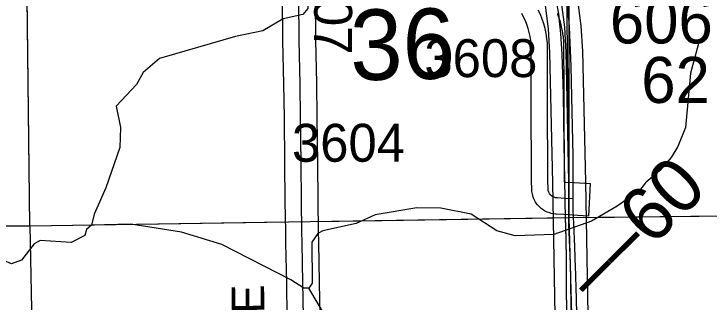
# Model space of a CAD drawing. Extents: x 23.6 to 68.7, y -63 to -29.
# Drawn here: x 43.707 to 44.988, y -51.736 to -51.204 of the extents above; entities that cross this region are included whole.
import ezdxf

# ---------------------------------------------------------------- set-up
doc = ezdxf.new("R2010")
doc.units = 0
for name, color, linetype in [('tdCoDivCarto', 7, 'Continuous'), ('tdCoHydroRiver', 7, 'Continuous'), ('tdCoPriCL', 7, 'Continuous'), ('tdCoPriDiv', 7, 'Continuous'), ('tdCoPrimary', 7, 'Continuous'), ('tdCoSecRdNmbr', 7, 'Continuous'), ('tdCoSecRdTxt', 7, 'Continuous'), ('tdCoSecRteBand', 7, 'Continuous'), ('tdCoSecRteCL', 7, 'Continuous'), ('tdCoSectLine', 7, 'Continuous'), ('tdCoSectLinePart', 7, 'Continuous'), ('tdCoSectNmbr', 7, 'Continuous'), ('tdCoStrucSecCoName', 7, 'Continuous'), ('tdCoStrucSecFHWANum', 7, 'Continuous'), ('tdCoSurfGravel', 7, 'Continuous'), ('tdCoTwpBndry', 7, 'Continuous'), ('tdCoTwpBndryShd', 7, 'Continuous'), ('tdStHwyPriRefPost1', 7, 'Continuous'), ('tdStHwyPriRefPost5', 7, 'Continuous')]:
    doc.layers.add(name, color=color, linetype=linetype)

msp = doc.modelspace()

# ---------------------------------------------------------------- linework, layer by layer
at = {"layer": 'tdCoDivCarto'}
for p, q in [((44.7304, -51.2183), (44.7201, -51.1354)), ((44.7304, -51.2183), (44.7293, -51.1793)), ((44.7103, -51.2035), (44.7105, -51.2055)), ((44.7105, -51.2055), (44.7142, -51.2401)), ((44.7309, -51.2279), (44.7304, -51.2183)), ((44.7341, -51.2999), (44.7309, -51.2279)), ((44.7142, -51.2401), (44.7164, -51.2781)), ((44.7164, -51.2781), (44.7179, -51.3156)), ((44.7354, -51.3847), (44.7341, -51.2999)), ((44.7179, -51.3156), (44.7183, -51.3329)), ((44.7183, -51.3329), (44.7188, -51.3523)), ((44.7188, -51.3523), (44.7203, -51.4443)), ((44.7373, -51.4649), (44.7354, -51.3847)), ((44.7203, -51.4443), (44.7221, -51.5441)), ((44.7373, -51.545), (44.7373, -51.4649)), ((44.7221, -51.5441), (44.723, -51.5846)), ((44.7373, -51.5665), (44.7373, -51.545)), ((44.7385, -51.5914), (44.7373, -51.5665)), ((44.723, -51.5846), (44.7232, -51.5939)), ((44.7406, -51.6331), (44.7385, -51.5914)), ((44.7232, -51.5939), (44.7245, -51.6539)), ((44.7419, -51.6729), (44.7406, -51.6331)), ((44.7245, -51.6539), (44.7246, -51.6659)), ((44.7246, -51.6659), (44.7247, -51.6852)), ((44.7246, -51.6659), (44.7247, -51.6852)), ((44.7423, -51.6829), (44.7419, -51.6729)), ((44.7423, -51.6829), (44.7419, -51.6729)), ((44.7425, -51.6895), (44.7423, -51.6829)), ((44.7247, -51.6852), (44.7248, -51.7095)), ((44.7247, -51.6852), (44.7248, -51.7095)), ((44.743, -51.7073), (44.7425, -51.6895)), ((44.7443, -51.7554), (44.743, -51.7073)), ((44.7248, -51.7095), (44.725, -51.754))]:
    msp.add_line(p, q, dxfattribs=at)
for points in [[(44.6843, -51.0826), (44.6868, -51.0888), (44.6905, -51.1011), (44.6964, -51.1248), (44.6991, -51.1413), (44.7103, -51.2035), (44.7105, -51.2055)], [(44.6843, -51.0826), (44.6868, -51.0888), (44.6905, -51.1011), (44.6964, -51.1248), (44.6991, -51.1413), (44.7103, -51.2035), (44.7105, -51.2055)], [(44.7309, -51.2279), (44.7304, -51.2183), (44.7293, -51.1793), (44.7254, -51.1263), (44.7241, -51.1111)], [(44.7309, -51.2279), (44.7304, -51.2183), (44.7293, -51.1793), (44.7254, -51.1263), (44.7241, -51.1111)], [(44.7309, -51.2279), (44.7304, -51.2183), (44.7293, -51.1793), (44.7254, -51.1263), (44.7241, -51.1111)], [(44.7304, -51.2183), (44.7201, -51.1354)], [(44.7304, -51.2183), (44.7201, -51.1354)], [(44.7304, -51.2183), (44.7201, -51.1354)], [(44.7103, -51.2035), (44.7142, -51.2401), (44.7164, -51.2781), (44.7179, -51.3156), (44.7183, -51.331)], [(44.7105, -51.2055), (44.7142, -51.2401), (44.7164, -51.2781), (44.7179, -51.3156), (44.7183, -51.3329)], [(44.7105, -51.2055), (44.7142, -51.2401), (44.7164, -51.2781), (44.7179, -51.3156), (44.7183, -51.3329)], [(44.7385, -51.5914), (44.7373, -51.5665), (44.7373, -51.545), (44.7373, -51.4649), (44.7354, -51.3847), (44.7341, -51.2999), (44.7309, -51.2279)], [(44.7385, -51.5914), (44.7373, -51.5665), (44.7373, -51.545), (44.7373, -51.4649), (44.7354, -51.3847), (44.7341, -51.2999), (44.7309, -51.2279)], [(44.7385, -51.5914), (44.7373, -51.5665), (44.7373, -51.545), (44.7373, -51.4649), (44.7354, -51.3847), (44.7341, -51.2999), (44.7309, -51.2279)], [(44.7183, -51.331), (44.7188, -51.3523), (44.7203, -51.4443), (44.7221, -51.5441), (44.723, -51.5846), (44.7232, -51.5919)], [(44.7183, -51.3329), (44.7188, -51.3523), (44.7203, -51.4443), (44.7221, -51.5441), (44.723, -51.5846), (44.7232, -51.5939)], [(44.7183, -51.3329), (44.7188, -51.3523), (44.7203, -51.4443), (44.7221, -51.5441), (44.723, -51.5846), (44.7232, -51.5939)], [(44.7232, -51.5919), (44.7245, -51.6539), (44.7246, -51.6639)], [(44.7419, -51.6729), (44.7406, -51.6331), (44.7385, -51.5914)], [(44.7419, -51.6729), (44.7406, -51.6331), (44.7385, -51.5914)], [(44.7419, -51.6729), (44.7406, -51.6331), (44.7385, -51.5914)], [(44.7232, -51.5939), (44.7245, -51.6539), (44.7246, -51.6659)], [(44.7232, -51.5939), (44.7245, -51.6539), (44.7246, -51.6659)], [(44.7246, -51.6639), (44.7247, -51.6832)], [(44.7246, -51.6659), (44.7247, -51.6852)], [(44.7247, -51.6832), (44.7248, -51.7075)], [(44.7423, -51.6829), (44.7419, -51.6729)], [(44.7423, -51.6829), (44.7419, -51.6729)], [(44.743, -51.7073), (44.7425, -51.6895), (44.7423, -51.6829)], [(44.743, -51.7073), (44.7425, -51.6895), (44.7423, -51.6829)], [(44.743, -51.7073), (44.7425, -51.6895), (44.7423, -51.6829)], [(44.7247, -51.6852), (44.7248, -51.7095)], [(44.7248, -51.7075), (44.725, -51.754), (44.7255, -51.7925)], [(44.745, -51.7922), (44.7447, -51.7798), (44.7443, -51.7554), (44.743, -51.7073)], [(44.745, -51.7922), (44.7447, -51.7798), (44.7443, -51.7554), (44.743, -51.7073)], [(44.745, -51.7922), (44.7447, -51.7798), (44.7443, -51.7554), (44.743, -51.7073)], [(44.7248, -51.7095), (44.725, -51.754), (44.7256, -51.7945)], [(44.7248, -51.7095), (44.725, -51.754), (44.7256, -51.7945)]]:
    msp.add_lwpolyline(points, dxfattribs=at)
at = {"layer": 'tdCoHydroRiver'}
for points in [[(44.2441, -50.8604), (44.2426, -50.8667), (44.2303, -50.8952), (44.2304, -50.9079), (44.2227, -50.93), (44.2233, -50.9948), (44.2299, -51.0231), (44.2379, -51.0404), (44.2428, -51.0498), (44.246, -51.0545), (44.2558, -51.0892), (44.2489, -51.1934), (44.2395, -51.2045), (44.2033, -51.2128), (44.1656, -51.2352), (44.1152, -51.2452), (43.9751, -51.286), (43.9453, -51.3117), (43.9329, -51.334), (43.8954, -51.374), (43.9037, -51.4135), (43.9025, -51.45), (43.8763, -51.5247)], [(44.9677, -51.2592), (44.9677, -51.2608), (44.9537, -51.3132), (44.9446, -51.4131), (44.9305, -51.4481), (44.918, -51.4688), (44.8975, -51.4928), (44.8707, -51.5153)], [(44.8707, -51.5153), (44.8597, -51.5296), (44.8187, -51.5586), (44.7713, -51.586), (44.7017, -51.6106), (44.6304, -51.6131), (44.5969, -51.6041), (44.5493, -51.573), (44.4939, -51.5625), (44.4497, -51.5613), (44.3725, -51.5747), (44.3379, -51.5908), (44.2765, -51.604), (44.2671, -51.6088), (44.2562, -51.6247), (44.2569, -51.7005), (44.2507, -51.71)], [(43.8763, -51.5247), (43.8547, -51.573), (43.8502, -51.5938)], [(43.8502, -51.5938), (43.8408, -51.6018), (43.8377, -51.6129), (43.8126, -51.6258), (43.7557, -51.6216), (43.7447, -51.628), (43.7213, -51.6582), (43.7025, -51.6647), (43.6739, -51.6524), (43.6581, -51.6493), (43.6345, -51.659), (43.5955, -51.6989), (43.5814, -51.7164), (43.5407, -51.7531), (43.4905, -51.7835), (43.4275, -51.7983), (43.3945, -51.8129), (43.3742, -51.8383), (43.3618, -51.8621), (43.3241, -51.883), (43.3132, -51.8926), (43.2945, -51.9275), (43.2507, -51.9674), (43.2334, -51.9723)], [(44.2507, -51.71), (44.2412, -51.7101), (44.2174, -51.6945), (44.0905, -51.6294), (44.016, -51.6065), (43.9228, -51.5916), (43.8502, -51.5938)], [(44.2811, -51.7618), (44.2507, -51.71)]]:
    msp.add_lwpolyline(points, dxfattribs=at)
at = {"layer": 'tdCoPriCL'}
msp.add_lwpolyline([(44.7494, -52.6208), (44.7496, -52.5866), (44.7497, -52.5565), (44.7457, -52.152), (44.7374, -51.9343), (44.7349, -51.7923), (44.7335, -51.7075), (44.7331, -51.6832), (44.7329, -51.6732), (44.7327, -51.6638), (44.7295, -51.5918), (44.7293, -51.5829), (44.7295, -51.5421), (44.7294, -51.5134), (44.7261, -51.3307), (44.7248, -51.274), (44.7219, -51.2283), (44.7069, -51.1127)], dxfattribs=at)
at = {"layer": 'tdCoPriDiv'}
for points in [[(44.7744, -55.3467), (44.7731, -54.7043), (44.7731, -54.578), (44.768, -54.3876), (44.7441, -54.1481), (44.7383, -53.8732), (44.7299, -53.6205), (44.72, -52.9192), (44.7194, -52.6207), (44.7158, -52.1528), (44.7074, -51.9351), (44.7002, -51.5156), (44.6948, -51.2752), (44.6921, -51.2312), (44.6796, -51.1348)], [(44.74, -51.1344), (44.7518, -51.2254), (44.7548, -51.2727), (44.7602, -51.5144), (44.7674, -51.9334), (44.7758, -52.1513), (44.7794, -52.6208), (44.78, -52.9184), (44.7899, -53.6189), (44.7983, -53.8716), (44.804, -54.1443), (44.8279, -54.384), (44.8331, -54.5775), (44.8331, -54.7034), (44.8344, -55.3459)]]:
    msp.add_lwpolyline(points, dxfattribs=at)
at = {"layer": 'tdCoPrimary'}
for p, q in [((44.7246, -51.6659), (44.7247, -51.6852)), ((44.7246, -51.6659), (44.7247, -51.6852)), ((44.7423, -51.6829), (44.7419, -51.6729)), ((44.7423, -51.6829), (44.7419, -51.6729)), ((44.7247, -51.6852), (44.7248, -51.7095)), ((44.7247, -51.6852), (44.7248, -51.7095))]:
    msp.add_line(p, q, dxfattribs=at)
for points in [[(44.7304, -51.2183), (44.7293, -51.1793), (44.7254, -51.1263), (44.7241, -51.1111), (44.7226, -51.0927), (44.7213, -51.0809), (44.7157, -51.0279), (44.7153, -51.0243), (44.7094, -50.9668), (44.7049, -50.9234), (44.6988, -50.8601), (44.6898, -50.7729), (44.6881, -50.7551), (44.6825, -50.6978), (44.6823, -50.6961), (44.6823, -50.6961), (44.6786, -50.667), (44.6698, -50.6455), (44.6684, -50.6438), (44.6683, -50.6438)], [(44.7304, -51.2183), (44.7201, -51.1354), (44.7132, -51.0962), (44.7104, -51.081), (44.7018, -51.0348), (44.6878, -50.9584), (44.6853, -50.943), (44.6823, -50.9278), (44.679, -50.9127), (44.6753, -50.8976), (44.6712, -50.8826), (44.6667, -50.8678), (44.6619, -50.8531), (44.652, -50.8252), (44.6439, -50.8055), (44.6386, -50.7933)], [(44.6843, -51.0826), (44.6868, -51.0888), (44.6905, -51.1011), (44.6964, -51.1248), (44.6991, -51.1413), (44.7103, -51.2035), (44.7105, -51.2055)], [(44.6843, -51.0826), (44.6868, -51.0888), (44.6905, -51.1011), (44.6964, -51.1248), (44.6991, -51.1413), (44.7103, -51.2035), (44.7105, -51.2055)], [(44.7309, -51.2279), (44.7304, -51.2183), (44.7293, -51.1793), (44.7254, -51.1263), (44.7241, -51.1111)], [(44.7309, -51.2279), (44.7304, -51.2183), (44.7293, -51.1793), (44.7254, -51.1263), (44.7241, -51.1111)], [(44.7304, -51.2183), (44.7201, -51.1354)], [(44.7304, -51.2183), (44.7201, -51.1354)], [(44.7103, -51.2035), (44.7105, -51.2055), (44.7142, -51.2401), (44.7164, -51.2781), (44.7179, -51.3156), (44.7183, -51.3329), (44.7188, -51.3523), (44.7203, -51.4443), (44.7221, -51.5441), (44.723, -51.5846), (44.7232, -51.5939), (44.7245, -51.6539), (44.7246, -51.6659), (44.7247, -51.6852), (44.7248, -51.7095), (44.725, -51.754)], [(44.7105, -51.2055), (44.7142, -51.2401), (44.7164, -51.2781), (44.7179, -51.3156), (44.7183, -51.3329)], [(44.7105, -51.2055), (44.7142, -51.2401), (44.7164, -51.2781), (44.7179, -51.3156), (44.7183, -51.3329)], [(44.7443, -51.7554), (44.743, -51.7073), (44.7425, -51.6895), (44.7423, -51.6829), (44.7419, -51.6729), (44.7406, -51.6331), (44.7385, -51.5914), (44.7373, -51.5665), (44.7373, -51.545), (44.7373, -51.4649), (44.7354, -51.3847), (44.7341, -51.2999), (44.7309, -51.2279), (44.7304, -51.2183)], [(44.7385, -51.5914), (44.7373, -51.5665), (44.7373, -51.545), (44.7373, -51.4649), (44.7354, -51.3847), (44.7341, -51.2999), (44.7309, -51.2279)], [(44.7385, -51.5914), (44.7373, -51.5665), (44.7373, -51.545), (44.7373, -51.4649), (44.7354, -51.3847), (44.7341, -51.2999), (44.7309, -51.2279)], [(44.7183, -51.3329), (44.7188, -51.3523), (44.7203, -51.4443), (44.7221, -51.5441), (44.723, -51.5846), (44.7232, -51.5939)], [(44.7183, -51.3329), (44.7188, -51.3523), (44.7203, -51.4443), (44.7221, -51.5441), (44.723, -51.5846), (44.7232, -51.5939)], [(44.7419, -51.6729), (44.7406, -51.6331), (44.7385, -51.5914)], [(44.7419, -51.6729), (44.7406, -51.6331), (44.7385, -51.5914)], [(44.7232, -51.5939), (44.7245, -51.6539), (44.7246, -51.6659)], [(44.7232, -51.5939), (44.7245, -51.6539), (44.7246, -51.6659)], [(44.743, -51.7073), (44.7425, -51.6895), (44.7423, -51.6829)], [(44.743, -51.7073), (44.7425, -51.6895), (44.7423, -51.6829)], [(44.745, -51.7922), (44.7447, -51.7798), (44.7443, -51.7554), (44.743, -51.7073)], [(44.745, -51.7922), (44.7447, -51.7798), (44.7443, -51.7554), (44.743, -51.7073)], [(44.7248, -51.7095), (44.725, -51.754), (44.7256, -51.7945)], [(44.7248, -51.7095), (44.725, -51.754), (44.7256, -51.7945)]]:
    msp.add_lwpolyline(points, dxfattribs=at)
at = {"layer": 'tdCoSecRteBand'}
for points in [[(44.2107, -51.7628), (44.2097, -51.7001), (44.2082, -51.6274), (44.2082, -51.6273), (44.2082, -51.6272), (44.2079, -51.6052), (44.2071, -51.5502), (44.2071, -51.5502), (44.2071, -51.5501), (44.2062, -51.479), (44.2062, -51.4789), (44.2062, -51.4789), (44.2054, -51.3956), (44.2046, -51.333), (44.2028, -51.2534), (44.2028, -51.2532), (44.2028, -51.253), (44.202, -51.1741)], [(44.262, -51.1736), (44.2628, -51.2522), (44.2646, -51.3318), (44.2646, -51.3319), (44.2646, -51.3321), (44.2654, -51.3949), (44.2654, -51.3949), (44.2654, -51.395), (44.2662, -51.4783), (44.2671, -51.5494), (44.2679, -51.6043), (44.2682, -51.6262), (44.2697, -51.699), (44.2697, -51.699), (44.2697, -51.6991), (44.2707, -51.7618)], [(44.7087, -51.2032), (44.7089, -51.204), (44.7118, -51.2127), (44.712, -51.2134), (44.7122, -51.2142), (44.7146, -51.223), (44.7148, -51.2238), (44.715, -51.2246), (44.7169, -51.2335), (44.7171, -51.2343), (44.7172, -51.2351), (44.7186, -51.2441), (44.7188, -51.2449), (44.7188, -51.2457), (44.7198, -51.2548), (44.72, -51.2564), (44.72, -51.2579), (44.72, -51.2769), (44.7202, -51.3221), (44.7202, -51.3222), (44.7202, -51.3223), (44.7202, -51.4029), (44.7207, -51.4686), (44.7207, -51.4686), (44.7207, -51.4687), (44.721, -51.5102), (44.721, -51.514), (44.7239, -51.5142), (44.7391, -51.5151), (44.7691, -51.5168), (44.7655, -51.5767), (44.7356, -51.575), (44.7204, -51.5741), (44.7062, -51.5733), (44.7055, -51.5732), (44.7047, -51.5731), (44.7019, -51.5728), (44.6994, -51.5725), (44.697, -51.5719), (44.6943, -51.5711), (44.6919, -51.5704), (44.6896, -51.5694), (44.6871, -51.5681), (44.6848, -51.5671), (44.6828, -51.5657), (44.6804, -51.5641), (44.6784, -51.5626), (44.6766, -51.5609), (44.6746, -51.5589), (44.6728, -51.5572), (44.6713, -51.5552), (44.6696, -51.5529), (44.6681, -51.5509), (44.667, -51.5487), (44.6657, -51.5462), (44.6646, -51.5439), (44.6639, -51.5416), (44.663, -51.5388), (44.6623, -51.5365), (44.6619, -51.534), (44.6615, -51.5312), (44.6613, -51.5293), (44.6612, -51.5275), (44.661, -51.511), (44.661, -51.5108), (44.661, -51.5107), (44.6607, -51.469), (44.6602, -51.4033), (44.6602, -51.4032), (44.6602, -51.403), (44.6602, -51.3223), (44.66, -51.2771), (44.66, -51.2771), (44.66, -51.277), (44.66, -51.2595), (44.6593, -51.2528), (44.6581, -51.2453), (44.6565, -51.2379), (44.6545, -51.2306), (44.6522, -51.2235), (44.6494, -51.2164), (44.6463, -51.2096), (44.6429, -51.2029)]]:
    msp.add_lwpolyline(points, dxfattribs=at)
at = {"layer": 'tdCoSecRteCL'}
for points in [[(44.2407, -51.7624), (44.2397, -51.6996), (44.2382, -51.6267), (44.2379, -51.6048), (44.2371, -51.5498), (44.2362, -51.4786), (44.2354, -51.3953), (44.2346, -51.3325), (44.2328, -51.2527), (44.232, -51.1738), (44.2318, -51.1046), (44.2318, -51.0864)], [(44.7373, -51.545), (44.7221, -51.5441), (44.708, -51.5433), (44.7052, -51.543), (44.7024, -51.5422), (44.6999, -51.541), (44.6975, -51.5394), (44.6955, -51.5374), (44.6938, -51.5351), (44.6925, -51.5326), (44.6916, -51.5298), (44.6912, -51.527), (44.691, -51.5105), (44.6907, -51.4688), (44.6902, -51.403), (44.6902, -51.3223), (44.69, -51.277), (44.69, -51.2579), (44.689, -51.2488), (44.6876, -51.2398), (44.6857, -51.2309), (44.6833, -51.222), (44.6804, -51.2133), (44.6771, -51.2048), (44.6733, -51.1965)]]:
    msp.add_lwpolyline(points, dxfattribs=at)
at = {"layer": 'tdCoSectLine'}
for points in [[(43.7365, -51.5949), (43.7248, -50.5884)], [(44.73, -50.5825), (44.7293, -51.5796)], [(43.7365, -51.5949), (44.7293, -51.5796)], [(44.7293, -51.5796), (45.7019, -51.569)], [(44.7293, -51.5796), (44.7461, -52.184), (44.7494, -52.6207)], [(42.7527, -51.5953), (43.7365, -51.5949)], [(43.7365, -51.5949), (43.7576, -52.6387)]]:
    msp.add_lwpolyline(points, dxfattribs=at)
at = {"layer": 'tdCoSectLinePart'}
for points in [[(44.7296, -51.1102), (44.7294, -51.5121)], [(43.7365, -51.5949), (43.731, -51.1202)], [(44.2674, -51.5867), (44.7293, -51.5796)], [(44.7293, -51.5721), (44.7293, -51.5796)], [(44.7293, -51.5796), (45.1782, -51.5747)], [(44.7293, -51.5796), (44.7461, -52.184), (44.7492, -52.5907)], [(43.7365, -51.5949), (44.2074, -51.5876)], [(43.2696, -51.5951), (43.7365, -51.5949)], [(43.7365, -51.5949), (43.7576, -52.6387)]]:
    msp.add_lwpolyline(points, dxfattribs=at)
at = {"layer": 'tdCoSurfGravel'}
for points in [[(44.2379, -51.6048), (44.2371, -51.5498), (44.2362, -51.4786), (44.2354, -51.3953), (44.2346, -51.3325), (44.2328, -51.2527), (44.232, -51.1738), (44.2318, -51.1046), (44.2318, -51.0864)], [(44.7373, -51.545), (44.7221, -51.5441), (44.708, -51.5433), (44.7052, -51.543), (44.7024, -51.5422), (44.6999, -51.541), (44.6975, -51.5394), (44.6955, -51.5374), (44.6938, -51.5351), (44.6925, -51.5326), (44.6916, -51.5298), (44.6912, -51.527), (44.691, -51.5105), (44.6907, -51.4688), (44.6902, -51.403), (44.6902, -51.3223), (44.69, -51.277), (44.69, -51.2579), (44.689, -51.2488), (44.6876, -51.2398), (44.6857, -51.2309), (44.6833, -51.222), (44.6804, -51.2133), (44.6771, -51.2048), (44.6733, -51.1965)], [(44.2407, -51.7624), (44.2397, -51.6996), (44.2382, -51.6267), (44.2379, -51.6048)]]:
    msp.add_lwpolyline(points, dxfattribs=at)
at = {"layer": 'tdCoTwpBndry'}
for points in [[(44.2673, -51.5867), (44.7013, -51.58)], [(44.7613, -51.5792), (45.1781, -51.5747)], [(43.2695, -51.5951), (43.7365, -51.5949), (44.2073, -51.5876)]]:
    msp.add_lwpolyline(points, dxfattribs=at)
at = {"layer": 'tdCoTwpBndryShd'}
for points in [[(43.7188, -49.8441), (43.7206, -50.071), (44.5531, -50.0557), (44.5706, -50.1659), (44.6521, -50.5976), (44.7246, -51.0894), (44.7293, -51.5796), (44.7461, -52.184), (44.7494, -52.6207), (44.7599, -53.6197), (44.7866, -54.6214), (44.8089, -55.6241), (44.8037, -55.6224), (44.8037, -55.6241), (44.8059, -56.6231), (44.8305, -57.6351)], [(39.7356, -51.6376), (40.7489, -51.6298), (41.7431, -51.6156), (42.7527, -51.5953), (43.7365, -51.5949), (44.7293, -51.5796), (45.7019, -51.569), (46.6986, -51.5546)]]:
    msp.add_lwpolyline(points, dxfattribs=at)

# ---------------------------------------------------------------- texts
at = {"layer": 'tdCoSecRdNmbr'}
for s, rotation, p in [('3607', 270.0323, (44.2602, -51.0702)), ('3608', 0.0334, (44.4634, -51.3204)), ('3604', 0.0345, (44.2194, -51.4766))]:
    msp.add_text(s, height=0.07, rotation=rotation, dxfattribs=at).set_placement(p)
at = {"layer": 'tdCoSecRdTxt'}
msp.add_text('LINCOLN AVE', height=0.06, rotation=90.7435, dxfattribs=at).set_placement((44.1749, -52.2333))
at = {"layer": 'tdCoSectNmbr'}
msp.add_text('36', height=0.13, rotation=1.0344, dxfattribs=at).set_placement((44.3275, -51.3263))
at = {"layer": 'tdCoStrucSecCoName'}
msp.add_text('62', height=0.085, dxfattribs=at).set_placement((44.863, -51.368))
at = {"layer": 'tdCoStrucSecFHWANum'}
msp.add_text('606720', height=0.085, dxfattribs=at).set_placement((44.8052, -51.2582))
at = {"layer": 'tdStHwyPriRefPost1'}
msp.add_text('‒‒60', height=0.1, rotation=45, dxfattribs=at).set_placement((44.7779, -51.7398))
at = {"layer": 'tdStHwyPriRefPost5'}
msp.add_text('‒‒60', height=0.1, rotation=45, dxfattribs=at).set_placement((44.7779, -51.7398))

doc.saveas('drawing.dxf')
